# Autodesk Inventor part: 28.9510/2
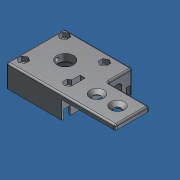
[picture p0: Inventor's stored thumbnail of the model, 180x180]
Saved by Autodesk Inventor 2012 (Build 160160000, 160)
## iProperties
Created: 2007-06
Part Number: 28.9510/2
Document SubType Name: Modeling
Designer: Andy Moles
Material: Aluminum-6061
Mass: 285.245 g
Surface Area: 355.533 cm^2
Volume: 105.256 cm^3
Density: 2.71 g/cm^3
Description: LR6 LEFT SET SCREW ACCESS
Author: Andy Moles
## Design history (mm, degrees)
sketch "Sketch1"
  geometry: L1 (-35, -39.5)-(-35, 34); L2 (-35, 34)-(51, 34); L3 (51, 34)-(51, 3); L4 (51, 3)-(103, 3); L5 (103, 3)-(103, -39.5); L6 (103, -39.5)-(-35, -39.5); C1 r 10.5 at (0, 0); C2 r 4.5 at (83, -17); C3 r 4.5 at (57, -17); C4 r 3.1 at (-27, 26); C5 r 3.1 at (27, 22.5); C6 r 3.1 at (-27, -26); C7 r 3.1 at (27, -22.5); 1 further point
  constraints: 12 end point, 7 centre point, 4 parallel, 2 vertical alignment, 1 coincident, 1 horizontal alignment, 1 perpendicular, 1 vertical
  dimensions: "d0" = 73.5 distance of L1.start L1.end; "d1" = 138 distance of L5.end L1.start; "d2" = 86 distance of L1.end L2.end; "d3" = 42.5 distance of L4.end L5.end; "d4" = 21 diameter of C1; "d5" = 35 distance from line of point (0, 0) L1; "d6" = 39.5 distance from line of point (0, 0) L6; "d7" = 9 diameter of C3; "d8" = 9 diameter of C2; "d9" = 22.5 distance from line of L6 C2.centre; "d10" = 6.2 diameter of C7; "d11" = 6.2 diameter of C5; "d12" = 6.2 diameter of C4; "d13" = 6.2 diameter of C6; "d14" = 20 distance from line of C2.centre L5; "d15" = 26 distance of C3.centre C2.centre; "d16" = 17 distance from line of L6 C7.centre; "d17" = 45 distance of C5.centre C7.centre; "d18" = 13.5 distance from line of C6.centre L6; "d19" = 52 distance of C4.centre C6.centre; "d20" = 54 horizontal distance of C5.centre C4.centre; "d21" = 8 distance from line of C4.centre L1
extrude "Extrusion1" new body sketch "Sketch1" distance "d22" = 28.5; taper "d23" = 0 deg
hole "Hole1" diameter "d26" = 8; stored, may be unused: countersink angle "d30" = 90 deg, drill point angle "d32" = 118 deg; dims "d24" = 10, "d25" = 10, "d27" = 6, "d28" = 17.5, "d29" = 2, "d31" = 8
hole "Hole2" diameter "d35" = 8; stored, may be unused: countersink angle "d39" = 90 deg, drill point angle "d41" = 118 deg; dims "d33" = 10, "d34" = 10, "d36" = 6, "d37" = 17.5, "d38" = 2, "d40" = 8
sketch "Sketch2"
  geometry: L1 (51, 34)-(51, 3) reference; L2 (-27, 31.976)-(-21.825, 28.988); L3 (-21.825, 28.988)-(-21.825, 23.012); L4 (-21.825, 23.012)-(-27, 20.024); L5 (-27, 20.024)-(-32.175, 23.012); L6 (-32.175, 23.012)-(-32.175, 28.988); L7 (-32.175, 28.988)-(-27, 31.976); L8 (32.175, 19.512)-(27, 16.524); L9 (27, 28.476)-(32.175, 25.488); L10 (21.825, 25.488)-(27, 28.476); L11 (21.825, 19.512)-(21.825, 25.488); L12 (27, 16.524)-(21.825, 19.512); L13 (32.175, 25.488)-(32.175, 19.512); L14 (-21.825, -28.988)-(-27, -31.976); L15 (-21.825, -23.012)-(-21.825, -28.988); L16 (-27, -20.024)-(-21.825, -23.012); L17 (-32.175, -23.012)-(-27, -20.024); L18 (-32.175, -28.988)-(-32.175, -23.012); L19 (-27, -31.976)-(-32.175, -28.988); L20 (32.175, -25.488)-(27, -28.476); L21 (32.175, -19.512)-(32.175, -25.488); L22 (27, -16.524)-(32.175, -19.512); L23 (21.825, -19.512)-(27, -16.524); L24 (21.825, -25.488)-(21.825, -19.512); L25 (27, -28.476)-(21.825, -25.488); C1 r 3.1 at (27, -22.5) reference; C2 r 3.1 at (-27, -26) reference; C3 r 3.1 at (27, 22.5) reference; C4 r 3.1 at (-27, 26) reference; 4 further points
  constraints: 48 end point, 20 equal length, 12 horizontal alignment, 4 midpoint, 4 vertical alignment, 1 parallel
  dimensions: "d42" = 10.35 distance between parallel lines of L4 L7; "d43" = 120 deg angle of L2 L7; "d44" = 10.35 distance between parallel lines of L8 L10; "d45" = 120 deg angle of L9 L10; "d46" = 120 deg angle of L13 L9; "d47" = 10.35 distance between parallel lines of L14 L17; "d48" = 120 deg angle of L16 L17; "d49" = 120 deg angle of L15 L16; "d50" = 10.35 distance between parallel lines of L20 L23; "d51" = 120 deg angle of L22 L23; "d52" = 120 deg angle of L21 L22
extrude "Extrusion2" cut sketch "Sketch2" distance "d53" = 6.1; taper "d54" = 0 deg
sketch "Sketch3"
  geometry: C1 r 10.5 at (0, 0) reference; C2 r 14.3 at (0, 0)
  constraints: 1 centre point, 1 coincident
  dimensions: "d55" = 28.6 diameter of C2
extrude "Extrusion3" cut sketch "Sketch3" distance "d56" = 19.5; taper "d57" = 0 deg
sketch "Sketch4"
  geometry: C1 r 14.3 at (0, 0) reference; C2 r 17.5 at (0, 0)
  constraints: 1 centre point, 1 coincident
  dimensions: "d58" = 35 diameter of C2
extrude "Extrusion4" cut sketch "Sketch4" distance "d59" = 17.5; taper "d60" = 0 deg
sketch "Sketch5"
  geometry: C1 r 17.5 at (0, 0) reference; C2 r 21 at (0, 0)
  constraints: 1 centre point, 1 coincident
  dimensions: "d61" = 42 diameter of C2
extrude "Extrusion5" cut sketch "Sketch5" distance "d62" = 17; taper "d63" = 0 deg
sketch "Sketch6"
  geometry: L1 (35, -39.5)-(35, 34) reference; L2 (-51, 34)-(-51, 3) reference; L3 (-51, 3)-(-103, 3) reference; L4 (-103, 3)-(-103, -39.5) reference; L5 (-103, -39.5)-(35, -39.5) reference; L6 (-51, 20.5)-(-35, 20.5); L7 (-35, 20.5)-(-35, -39.5); C1 r 4.5 at (-57, -17) reference; C2 r 4.5 at (-83, -17) reference
  constraints: 4 end point, 2 point on line, 1 parallel, 1 perpendicular
  dimensions: "d64" = 70 distance between parallel lines of L7 L1; "d65" = 60 distance between parallel lines of L5 L6
extrude "Extrusion6" cut sketch "Sketch6" distance "d66" = 22.5; taper "d67" = 0 deg
fillet "Fillet1" dims "d68" = 2
sketch "Sketch7"
  geometry: L1 (0, 0)-(22.5, 0) reference; L2 (0, -17.5)-(-4, -17.5) reference; L3 (0, -17.5)-(0, -15.5) reference; L4 (2.5, -14.5)-(2.5, -4.5); L5 (0, -15.842)-(0, 0); L6 (0, 0)-(7, 0); A1 r 3 centre (2.5, -17.5) between (2.5, -14.5) and (-0.5, -17.5); A2 r 4.5 centre (7, -4.5) between (7, 0) and (2.5, -4.5); 1 further point
  constraints: 6 end point, 5 point on circle, 3 point on line, 3 tangent, 2 centre point, 2 collinear, 1 horizontal alignment, 1 parallel, 1 vertical alignment
  dimensions: "d69" = 6 diameter of A1; "d70" = 2.5 distance from line of L3 A1.centre; "d71" = 9 diameter of A2
extrude "Extrusion7" join sketch "Sketch7" distance "d72" = 16; taper "d73" = 0 deg
sketch "Sketch8"
  geometry: L1 (-66.982, -10.307)-(-57, -10.307); L2 (-66.982, -23.693)-(-57, -23.693); C1 r 4.5 at (-57, -17) reference; A1 r 6.693 centre (-57, -17) between (-57, -23.693) and (-57, -10.307); A2 r 6.693 centre (-66.982, -17) between (-66.982, -10.307) and (-66.982, -23.693); 1 further point
  constraints: 4 end point, 4 point on circle, 3 tangent, 2 centre point, 1 coincident, 1 horizontal, 1 parallel
  dimensions: "d75" = 13.3858 diameter of A1; "d76" = 13.3858 diameter of A2 (= d75); "d77" = 23.368 dimension on A1 A2
extrude "Extrusion8" cut sketch "Sketch8" distance "d78" = 2; taper "d79" = 0 deg
sketch "Sketch9"
  geometry: L1 (-51, 32)-(-51, 20.5) reference; L2 (-51, 20.5)-(-35, 20.5) reference; L3 (-35, 20.5)-(-35, -39.5) reference; L4 (-35, -39.5)-(33, -39.5) reference; L5 (0, 31)-(-51, 31); L6 (0, -31)-(-12.5, -31); L7 (-35, -37)-(-12.5, -31); L8 (-51, 25.8)-(-33.093, 25.8); C1 r 21 at (0, 0) reference; A1 r 3.1 centre (-27, 22.5) between (-30.096, 22.652) and (-28.263, 19.669) reference; A2 r 3.1 centre (-27, -22.5) between (-30.062, -22.986) and (-28.263, -19.669) reference; A3 r 5 centre (-35, -23.769) between (-35, -28.769) and (-30.062, -22.986); A4 r 3 centre (-29.486, -16.929) between (-28.263, -19.669) and (-26.884, -15.436); A5 r 3 centre (-29.486, 16.929) between (-26.884, 15.436) and (-28.263, 19.669); A6 r 3 centre (-33.093, 22.8) between (-30.096, 22.652) and (-33.093, 25.8); A7 r 3.109 centre (-33.093, 22.8) between (-35.184, 20.5) and (-35, 20.345); A8 r 31 centre (0, 0) between (-26.884, 15.436) and (-26.884, -15.436); A9 r 31 centre (0, 0) between (0, -31) and (0, 31)
  constraints: 18 point on circle, 9 tangent, 8 end point, 7 centre point, 7 point on line, 2 parallel, 1 coincident, 1 perpendicular
  dimensions: "d81" = 2.5 distance from line of L7.start L4; "d82" = 22.5 distance from line of L6.end L3; "d83" = 10 diameter of A3; "d84" = 6 diameter of A4; "d85" = 6 diameter of A5; "d88" = 3 radius of A6; "d89" = 0.2 distance edge to line of A1 L8; "d90" = 31 radius of A9; "d91" = 31 radius of A8
extrude "Extrusion9" cut sketch "Sketch9" distance "d92" = 11; taper "d93" = 0 deg
sketch "Sketch11"
  geometry: L1 (0, -2)-(26.5, -2) reference; L2 (28.5, 0)-(28.5, 69.5) reference; C1 r 2 at (19, 26); 1 further point
  constraints: 1 centre point
  dimensions: "d96" = 4 diameter of C1; "d97" = 9.5 distance from line of C1.centre L2; "d98" = 28 distance from line of C1.centre L1
extrude "Extrusion10" cut sketch "Sketch11" stored distance "d99" = 11; taper "d100" = 0 deg
hole "Hole3" diameter "d103" = 6.5; stored, may be unused: countersink angle "d107" = 90 deg, drill point angle "d109" = 0 deg; dims "d101" = 10, "d102" = 10, "d104" = 6, "d105" = 17.5, "d106" = 2, "d108" = 25
sketch "Sketch12"
  geometry: L1 (-26, -15.032)-(-10, -15.032); L2 (-10, -15.032)-(-10, -8.032); L3 (-10, -8.032)-(-26, -8.032); L4 (-26, -8.032)-(-26, -15.032); L5 (-10, -9.564)-(-10, -13.5) reference; L6 (-35, 20.5)-(-35, -28.769) reference; 3 further points
  constraints: 8 end point, 3 midpoint, 2 parallel, 1 horizontal, 1 horizontal alignment, 1 perpendicular
  dimensions: "d110" = 7 distance of L3.end L1.start; "d111" = 9 distance between parallel lines of L4 L6
extrude "Extrusion11" cut sketch "Sketch12" distance "d112" = 8; taper "d113" = 0 deg
sketch "Sketch10" dims "d94" = 57, "d95" = 45
  geometry: L1 (0, 31)-(-51, 31) reference; L2 (-20.408, 9.473)-(-25.621, 12.483); L3 (-27.997, -5.332)-(-21.859, -5.332); L4 (-27.191, 14.887)-(-30.922, 16.929); L5 (3.869, 22.165)-(5.426, 27.979); L6 (-26, -8.032)-(-19.403, -8.032) reference; L7 (-18.408, 12.938)-(-23.621, 15.947); L8 (-23.015, 10.978)-(-21.015, 14.442); L9 (-24.682, 14.25)-(0, 0); L10 (7.732, 21.13)-(9.29, 26.943); L11 (4.647, 25.072)-(8.511, 24.037); L12 (0, 0)-(7.376, 27.529); L13 (22.411, 2)-(28.43, 2); L14 (22.411, -2)-(28.43, -2); L15 (25.42, -2)-(25.42, 2); L16 (0, 0)-(28.5, 0); L17 (4.647, -25.072)-(8.511, -24.037); L18 (6.579, -24.554)-(0, 0); L19 (3.869, -22.165)-(5.426, -27.979); L20 (7.732, -21.13)-(9.29, -26.943); L21 (-22.312, -17.732)-(-13.85, -17.732); L22 (-14.664, -15.032)-(-26, -15.032) reference; A1 r 31 centre (0, 0) between (-26.884, 15.436) and (-26.884, -15.436) reference; A2 r 31 centre (0, 0) between (0, -31) and (0, 31) reference; 4 further points
  constraints: 38 end point, 12 midpoint, 8 parallel, 3 point on line, 2 coincident, 2 perpendicular, 1 horizontal, 1 point on circle, 27 other
  dimensions: "d114" = 2.7 distance between parallel lines of L3 L6; "d116" = 4 distance between parallel lines of L7 L2; "d117" = 4 distance from line of L10 L5.end; "d118" = 4 distance of L14.end L13.end; "d119" = 75 deg angle of L16 L12; "d121" = 75 deg angle of L16 L18 (= d119); "d122" = 4 distance between parallel lines of L20 L19; "d123" = 2.7 distance between parallel lines of L22 L21; "d124" = 75 deg angle of L12 L9 (= d119)
extrude "Extrusion12" cut sketch "Sketch10" distance "d125" = 7.5; taper "d126" = 0 deg
sketch "Sketch13"
  geometry: L1 (26.848, -9.564)-(20.366, -9.564) reference; L2 (28.43, -2)-(22.411, -2) reference; L3 (15.819, -16)-(23.585, -16); L4 (21.383, -7)-(27.627, -7); L5 (18.047, -13.436)-(25.134, -13.436) reference; A1 r 28.5 centre (0, 0) between (26.848, -9.564) and (28.43, -2) reference; A2 r 22.5 centre (0, 0) between (20.366, -9.564) and (22.411, -2) reference; A3 r 22.5 centre (0, 0) between (7.732, -21.13) and (18.047, -13.436) reference; A4 r 28.5 centre (0, 0) between (9.29, -26.943) and (25.134, -13.436) reference; A5 r 22.5 centre (0, 0) between (15.819, -16) and (21.383, -7); A6 r 22.5 centre (0, 0) between (22.411, -2) and (22.5, 0); A7 r 22.5 centre (0, 0) between (-18.047, -13.436) and (-15.819, -16); A8 r 28.5 centre (0, 0) between (28.5, 0) and (9.29, -26.943); A9 r 28.5 centre (0, 0) between (23.585, -16) and (27.627, -7)
  constraints: 19 point on circle, 5 centre point, 5 end point, 2 coincident, 2 parallel, 2 point on line
  dimensions: "d128" = 9 distance between parallel lines of L4 L3; "d129" = 3.87298 distance between parallel lines of L5 L1 (derived); "d130" = 2.56351 distance between parallel lines of L4 L1 (= -0.5 x d129 + 0.5 x d128)
extrude "Extrusion13" join sketch "Sketch13" distance "d131" = 4; taper "d132" = 0 deg
hole "Hole4" diameter "d135" = 4; stored, may be unused: countersink angle "d139" = 90 deg, drill point angle "d141" = 118 deg; dims "d133" = 10, "d134" = 10, "d136" = 6, "d137" = 17.5, "d138" = 2, "d140" = 25
sketch "Sketch15"
  geometry: L1 (27, -16.524)-(32.175, -19.512) reference; L2 (32.175, -19.512)-(32.175, -16.524); L3 (21.825, -19.512)-(27, -16.524) reference; L4 (-33, -37.5)-(-33, 32) reference; L5 (25.675, -17.289)-(25.675, -16.524); L6 (32.175, -16.524)-(25.675, -16.524)
  constraints: 6 end point, 2 point on line, 1 parallel, 1 perpendicular, 1 vertical
  dimensions: "d146" = 6.5 distance of L2.end L5.end
extrude "Extrusion14" cut sketch "Sketch15" distance "d144" = 6.1; taper "d145" = 0 deg
sketch "Sketch16"
  geometry: L1 (6.1, 8.963)-(0, 8.963) reference; L2 (6.1, 8.963)-(6.1, 18.512); L3 (6.1, 18.512)-(-6.143, 18.512); L4 (-6.143, 18.512)-(-8.9, 13.738); L5 (-8.9, 13.738)-(-6.143, 8.963); L6 (6.1, -2.988)-(0, -2.988) reference; L7 (-6.143, 8.963)-(6.1, 8.963); 1 further point
  constraints: 10 end point, 2 perpendicular, 1 collinear, 1 equal length, 1 horizontal alignment, 1 vertical alignment
  dimensions: "d147" = 21.5 distance between parallel lines of L3 L6; "d148" = 120 deg angle of L5 L4; "d149" = 15 distance from line of L4.end L2
extrude "Extrusion15" cut sketch "Sketch16" distance "d150" = 6.5; taper "d151" = 0 deg
sketch "Sketch17"
  geometry: L1 (22.5, 60)-(22.5, 10.731) reference; L2 (3.5, 31.35)-(22.5, 31.35); L3 (3.5, 24.65)-(22.5, 24.65); L4 (22.5, 31.35)-(22.5, 24.65); C1 r 3.25 at (3.5, 28) reference; A1 r 3.35 centre (3.5, 28) between (3.5, 31.35) and (3.5, 24.65); 1 further point
  constraints: 6 end point, 2 point on circle, 2 point on line, 2 tangent, 1 centre point, 1 coincident, 1 collinear, 1 parallel, 1 perpendicular
  dimensions: "d152" = 3.35 radius of A1
extrude "Extrusion16" cut sketch "Sketch17" distance "d153" = 3; taper "d154" = 0 deg
sketch "Sketch18"
  geometry: 2 further points
extrude "Extrusion17" cut sketch "Sketch18" distance "d155" = 35; taper "d156" = 0 deg
body "Solid1"
node "Reference1"
other parameters: "d80" = 62, "d87" = 6
